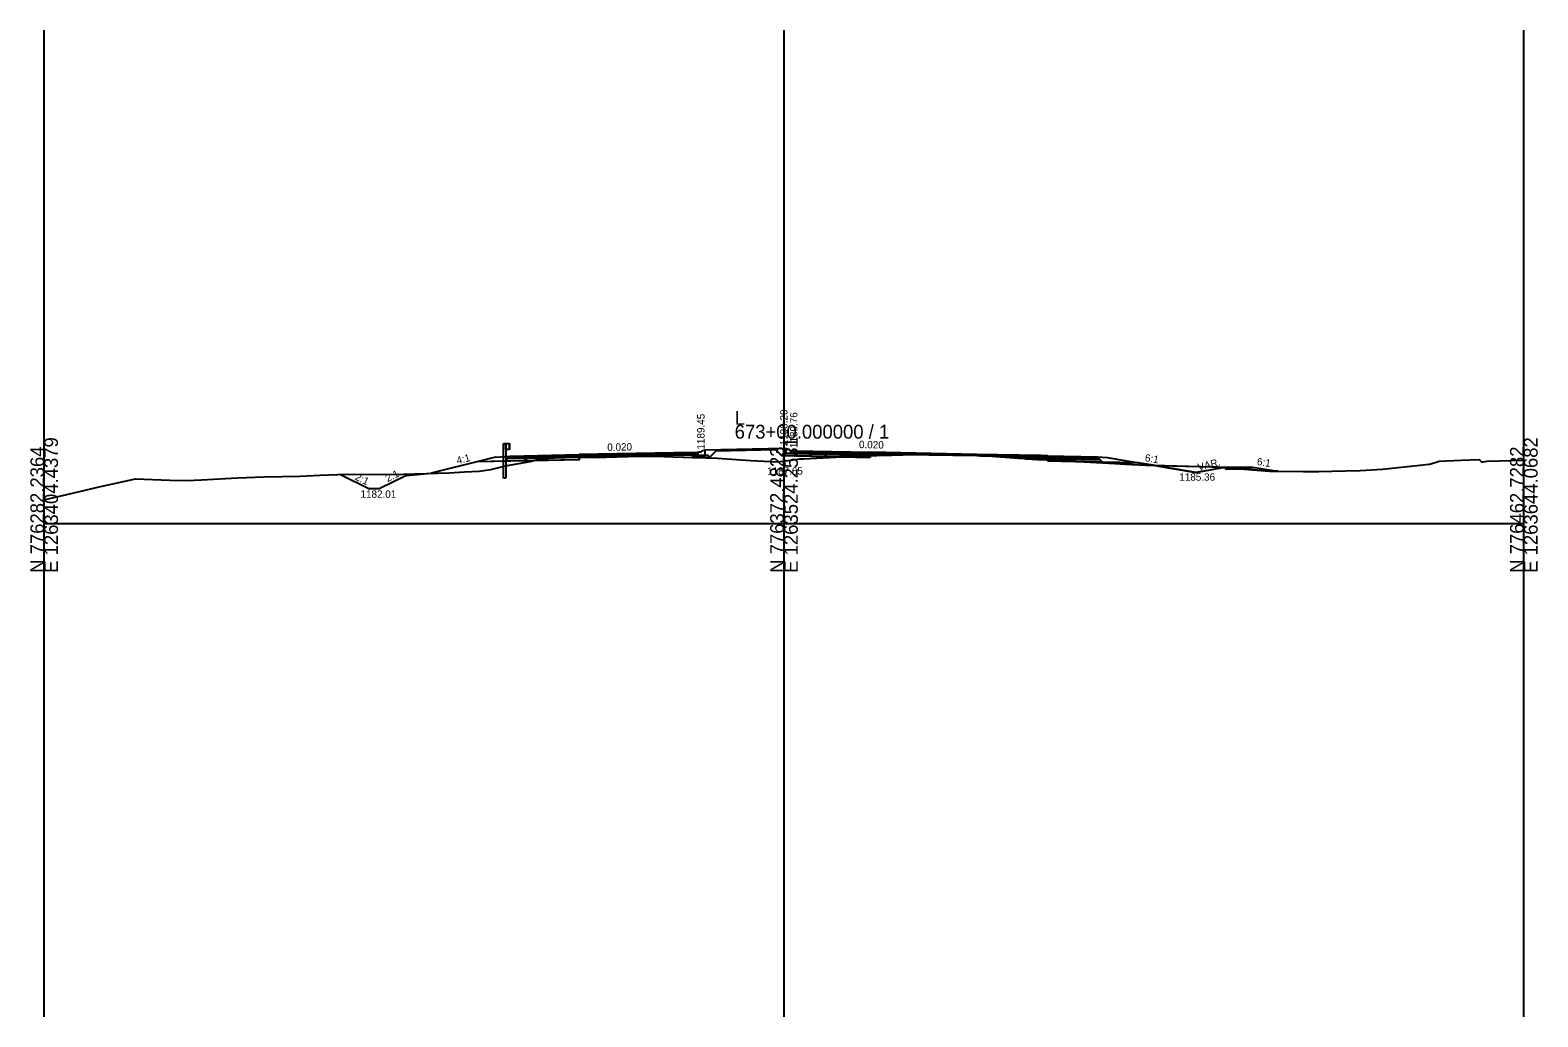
# Model space of a CAD drawing. Extents: x -41 to 1262860, y -100 to 777489.
# Drawn here: x 497.2 to 802.8, y 115 to 315 of the extents above; entities that cross this region are included whole.
import ezdxf

# ---------------------------------------------------------------- set-up
doc = ezdxf.new("R2010")
doc.units = 0
for name, color, linetype in [('Exist Cross Section Cell', 7, 'Continuous'), ('Exist XS Center Line Elevation Label', 7, 'Continuous'), ('Exist XS Ground Line', 7, 'Continuous'), ('Prop CMT Guardrail Graphics', 7, 'Continuous'), ('Prop CMT Pvmt Concrete', 7, 'Continuous'), ('Prop CMT Pvmt Course 1', 7, 'Continuous'), ('Prop CMT Pvmt Course 4', 7, 'Continuous'), ('Prop CMT Pvmt Surface', 7, 'Continuous'), ('Prop CMT Shld Paved Course 1', 7, 'Continuous'), ('Prop CMT Shld Paved Course 2', 7, 'Continuous'), ('Prop CMT Shld Paved Course 4', 7, 'Continuous'), ('Prop CMT Subgrade Earthwork', 7, 'Continuous'), ('Prop Conc Curb and Gutter', 7, 'Continuous'), ('Prop Conc Island Cover', 7, 'Continuous'), ('Prop XS Ditch Standard Text', 7, 'Continuous'), ('Prop XS Earthwork Shape', 7, 'Continuous'), ('Prop XS Elevation Labels', 7, 'Continuous'), ('Prop XS Exc Vertical Line 1', 7, 'Continuous'), ('Prop XS Exc Vertical Line 2', 7, 'Continuous'), ('Prop XS Exc Vertical Line 3', 7, 'Continuous'), ('Prop XS Finish Grade', 7, 'Continuous'), ('Prop XS Hydro Elevations', 7, 'Continuous'), ('Prop XS SE Text', 7, 'Continuous'), ('Prop XS Side Slope Text', 7, 'Continuous'), ('Scratch_Level_1', 7, 'Continuous'), ('Scratch_Level_4', 7, 'Continuous'), ('Scratch_Level_6', 7, 'Continuous')]:
    doc.layers.add(name, color=color, linetype=linetype)

msp = doc.modelspace()

# ---------------------------------------------------------------- linework, layer by layer
at = {"layer": 'Exist Cross Section Cell'}
for p, q in [((650, 215), (650, 235)), ((500, 215), (650, 215)), ((650, 215), (800, 215))]:
    msp.add_line(p, q, dxfattribs=at)
at = {"layer": 'Exist XS Ground Line'}
msp.add_lwpolyline([(500, 219.77), (500.55, 219.9), (506.89, 221.42), (511.4, 222.5), (513.89, 223.03), (518.54, 224.04), (525.5, 223.81), (528.95, 223.71), (531.89, 223.88), (539.2, 224.25), (544.63, 224.43), (551.91, 224.62), (555.97, 224.83), (561.37, 224.97), (569.37, 224.96), (572.82, 225.02), (582.14, 225.28), (585.2, 225.48), (588.22, 225.61), (590.59, 225.97), (593.51, 226.7), (598.55, 227.59), (599.77, 227.93), (601.37, 228.12), (602.72, 228.29), (603.5, 228.3), (607.89, 228.45), (609.08, 228.47), (611.68, 228.37), (620.56, 228.62), (624.04, 228.65), (627.52, 228.54), (636.51, 228.21), (637.48, 228.16), (639.45, 228.06), (643.3, 227.78), (648.7, 227.47), (651.31, 227.83), (653.19, 228.08), (653.8, 228.12), (653.99, 228.13), (662.73, 228.56), (665.83, 228.72), (671.78, 228.88), (677.74, 229.03), (679.36, 229), (689.76, 228.82), (692.13, 228.67), (698.7, 228.16), (699.03, 228.13), (699.07, 228.13), (701.34, 227.96), (703.63, 227.92), (704.66, 227.9), (717.07, 227.15), (719.26, 227), (723.37, 226.84), (736.84, 226.5), (737.79, 226.48), (737.89, 226.48), (738.17, 226.45), (748.46, 225.62), (755.35, 225.55), (758.45, 225.57), (763.86, 225.69), (766.8, 225.72), (771.35, 226.03), (778.98, 226.8), (780.75, 227.01), (780.95, 227.06), (782.86, 227.61), (787.3, 227.84), (790.97, 227.95), (791.05, 227.87), (791.47, 227.45), (791.75, 227.49), (792.54, 227.64), (800, 227.84)], dxfattribs=at)
at = {"layer": 'Prop CMT Guardrail Graphics'}
for p, q in [((593.11, 231.19), (593.59, 231.19)), ((593.11, 228.69), (593.11, 231.19)), ((593.59, 230.01), (593.59, 231.19)), ((593.59, 231.19), (594.26, 231.19)), ((593.59, 231.19), (593.59, 228.68)), ((594.26, 230.01), (593.59, 230.01)), ((594.26, 231.19), (594.26, 230.01)), ((594.26, 231.11), (594.26, 230.09)), ((594.36, 231.09), (594.26, 231.11)), ((594.26, 230.09), (594.36, 230.11)), ((594.27, 230.64), (594.5, 230.84)), ((594.27, 230.55), (594.27, 230.64)), ((594.5, 230.35), (594.27, 230.55)), ((594.5, 230.99), (594.36, 231.09)), ((594.36, 230.11), (594.5, 230.21)), ((594.5, 230.84), (594.5, 230.99)), ((594.5, 230.21), (594.5, 230.35)), ((593.11, 224.18), (593.11, 228.69)), ((593.59, 228.68), (593.59, 224.18)), ((593.59, 224.18), (593.11, 224.18))]:
    msp.add_line(p, q, dxfattribs=at)
at = {"layer": 'Prop CMT Pvmt Concrete'}
for p, q in [((739.5, 226.34), (744.5, 226.44)), ((739.5, 226.34), (739.5, 226.01)), ((744.5, 226.44), (744.5, 226.11)), ((739.5, 226.01), (744.5, 226.11))]:
    msp.add_line(p, q, dxfattribs=at)
at = {"layer": 'Prop CMT Pvmt Course 1'}
for p, q in [((632.5, 229.19), (632.5, 229.44)), ((651.96, 229.75), (651.96, 229.5)), ((651.96, 229.5), (667.5, 229.19)), ((631.5, 229.17), (632.5, 229.19))]:
    msp.add_line(p, q, dxfattribs=at)
for points in [[(608.5, 228.96), (608.5, 228.71), (608.5, 228.71), (631.5, 229.17), (631.5, 229.17), (631.5, 229.42), (631.5, 229.42), (631.5, 229.42), (608.5, 228.96), (608.5, 228.96), (608.5, 228.96)], [(703.5, 228.72), (703.5, 228.72), (702.06, 228.75), (702.06, 228.75), (701.97, 228.75), (701.97, 228.75), (701.97, 228.75), (689.08, 229.01), (689.08, 229.01), (670.64, 229.37), (670.57, 229.38), (670.57, 229.38), (670.45, 229.38), (670.45, 229.38), (670.32, 229.38), (670.32, 229.38), (670.17, 229.38), (670.17, 229.38), (670.04, 229.39), (670.04, 229.39), (669.93, 229.39), (669.93, 229.39), (669.87, 229.39), (669.87, 229.39), (667.5, 229.44), (667.5, 229.44), (667.5, 229.44), (667.5, 229.19), (667.5, 229.19), (669.87, 229.14), (669.87, 229.14), (669.93, 229.14), (669.93, 229.14), (670.04, 229.14), (670.04, 229.14), (670.17, 229.13), (670.17, 229.13), (670.32, 229.13), (670.32, 229.13), (670.45, 229.13), (670.45, 229.13), (670.57, 229.13), (670.57, 229.13), (670.64, 229.12), (689.08, 228.76), (689.08, 228.76), (701.97, 228.5), (701.97, 228.5), (701.97, 228.5), (702.06, 228.5), (702.06, 228.5), (703.5, 228.47), (703.5, 228.72)]]:
    msp.add_lwpolyline(points, dxfattribs=at)
at = {"layer": 'Prop CMT Pvmt Course 4'}
for p in [(593.9, 228.08), (608.5, 227.92)]:
    msp.add_line(p, (593.44, 227.61), dxfattribs=at)
at = {"layer": 'Prop CMT Pvmt Surface'}
for p, q in [((608.5, 228.96), (631.5, 229.42)), ((631.5, 229.42), (632.5, 229.44)), ((651.96, 229.75), (667.5, 229.44)), ((667.5, 229.44), (703.5, 228.72)), ((594.5, 228.68), (608.5, 228.96)), ((703.5, 228.72), (713.5, 228.52))]:
    msp.add_line(p, q, dxfattribs=at)
at = {"layer": 'Prop CMT Shld Paved Course 1'}
for p, q in [((608.5, 228.71), (594.24, 228.42)), ((594.5, 228.68), (594.24, 228.42)), ((604.5, 228.88), (604.5, 228.88)), ((608.5, 228.96), (608.5, 228.71)), ((608.5, 228.71), (608.5, 228.71)), ((703.5, 228.72), (703.5, 228.47)), ((703.5, 228.47), (703.5, 228.47)), ((703.5, 228.47), (713.76, 228.26)), ((707.5, 228.64), (707.5, 228.64)), ((713.76, 228.26), (713.5, 228.52))]:
    msp.add_line(p, q, dxfattribs=at)
at = {"layer": 'Prop CMT Shld Paved Course 2'}
for p, q in [((651.96, 229.16), (651.96, 229.5)), ((593.9, 228.08), (594.24, 228.42)), ((608.5, 228.37), (593.9, 228.08)), ((603.9, 228.28), (603.9, 228.28)), ((603.9, 228.28), (603.9, 228.28)), ((608.5, 228.71), (609.08, 228.72)), ((608.5, 228.71), (608.5, 228.37)), ((608.5, 228.46), (608.5, 228.71)), ((608.5, 228.71), (608.5, 228.71)), ((609.08, 228.47), (608.5, 228.46)), ((608.5, 228.37), (608.5, 228.37)), ((609.08, 228.72), (611.68, 228.77)), ((609.08, 228.72), (609.08, 228.72)), ((610.49, 228.41), (609.08, 228.47)), ((609.08, 228.47), (609.08, 228.47)), ((611.68, 228.44), (610.49, 228.41)), ((610.49, 228.41), (610.49, 228.41)), ((611.68, 228.77), (620.56, 228.95)), ((611.68, 228.77), (611.68, 228.77)), ((611.68, 228.77), (611.68, 228.77)), ((619.49, 228.59), (611.68, 228.44)), ((611.68, 228.44), (611.68, 228.44)), ((620.56, 228.62), (619.49, 228.59)), ((619.49, 228.59), (619.49, 228.59)), ((620.56, 228.95), (624.04, 229.02)), ((620.56, 228.95), (620.56, 228.95)), ((621.34, 228.63), (620.56, 228.62)), ((624.04, 228.68), (621.34, 228.63)), ((624.04, 229.02), (627.52, 229.09)), ((627.52, 228.75), (624.04, 228.68)), ((624.04, 228.68), (624.04, 228.68)), ((627.52, 229.09), (631.5, 229.17)), ((627.52, 229.09), (627.52, 229.09)), ((627.52, 229.09), (627.52, 229.09)), ((627.52, 229.09), (627.52, 229.09)), ((631.5, 228.83), (627.52, 228.75)), ((627.52, 228.75), (627.52, 228.75)), ((627.52, 228.75), (627.52, 228.75)), ((627.52, 228.75), (627.52, 228.75)), ((631.5, 229.17), (631.5, 229.17)), ((631.5, 229.17), (631.5, 229.17)), ((631.5, 229.17), (631.5, 228.83)), ((631.5, 228.83), (632.5, 228.85)), ((631.5, 228.83), (631.5, 228.83)), ((632.5, 229.19), (632.5, 228.85)), ((651.96, 229.16), (667.5, 228.85)), ((669.87, 229.14), (667.5, 229.19)), ((667.5, 229.19), (667.5, 229.19)), ((667.5, 229.19), (667.5, 229.19)), ((667.5, 229.19), (667.5, 229.19)), ((667.5, 229.19), (667.5, 228.85)), ((667.5, 228.85), (667.5, 228.85)), ((667.5, 228.85), (669.45, 228.81)), ((669.45, 228.81), (669.87, 228.83)), ((669.45, 228.81), (669.45, 228.81)), ((669.45, 228.81), (669.45, 228.81)), ((669.93, 229.14), (669.87, 229.14)), ((669.87, 229.14), (669.87, 229.14)), ((669.87, 228.83), (669.87, 228.83)), ((669.87, 228.83), (669.93, 228.83)), ((670.04, 229.14), (669.93, 229.14)), ((669.93, 229.14), (669.93, 229.14)), ((669.93, 228.83), (669.93, 228.83)), ((669.93, 228.83), (670.04, 228.83)), ((670.17, 229.13), (670.04, 229.14)), ((670.04, 229.14), (670.04, 229.14)), ((670.04, 228.83), (670.04, 228.83)), ((670.04, 228.83), (670.17, 228.83)), ((670.32, 229.13), (670.17, 229.13)), ((670.17, 229.13), (670.17, 229.13)), ((670.17, 228.83), (670.32, 228.84)), ((670.17, 228.83), (670.17, 228.83)), ((670.45, 229.13), (670.32, 229.13)), ((670.32, 229.13), (670.32, 229.13)), ((670.32, 228.84), (670.32, 228.84)), ((670.32, 228.84), (670.45, 228.84)), ((670.57, 229.13), (670.45, 229.13)), ((670.45, 229.13), (670.45, 229.13)), ((670.45, 228.84), (670.57, 228.85)), ((670.45, 228.84), (670.45, 228.84)), ((670.64, 229.12), (670.57, 229.13)), ((670.57, 229.13), (670.57, 229.13)), ((670.57, 228.85), (670.57, 228.85)), ((670.57, 228.85), (670.64, 228.85)), ((671.78, 229.1), (670.64, 229.12)), ((670.64, 228.85), (671.78, 228.88)), ((677.74, 228.98), (671.78, 229.1)), ((671.78, 229.1), (671.78, 229.1)), ((671.78, 228.88), (676.62, 229)), ((671.78, 228.88), (671.78, 228.88)), ((676.62, 229), (676.62, 229)), ((676.62, 229), (677.74, 228.98)), ((679.36, 228.95), (677.74, 228.98)), ((677.74, 228.98), (679.36, 228.95)), ((689.08, 228.76), (679.36, 228.95)), ((679.36, 228.95), (679.36, 228.95)), ((679.36, 228.95), (679.36, 228.95)), ((679.36, 228.95), (689.08, 228.76)), ((689.76, 228.74), (689.08, 228.76)), ((689.08, 228.76), (689.08, 228.76)), ((689.08, 228.76), (689.08, 228.76)), ((689.08, 228.76), (689.76, 228.74)), ((692.13, 228.69), (689.76, 228.74)), ((689.76, 228.74), (689.76, 228.74)), ((689.76, 228.74), (689.76, 228.74)), ((689.76, 228.74), (691.5, 228.71)), ((691.5, 228.71), (691.5, 228.71)), ((691.5, 228.71), (691.5, 228.71)), ((691.5, 228.71), (692.13, 228.67)), ((698.7, 228.56), (692.13, 228.69)), ((692.13, 228.69), (692.13, 228.69)), ((692.13, 228.69), (692.13, 228.69)), ((692.13, 228.67), (692.13, 228.67)), ((692.13, 228.67), (692.13, 228.67)), ((692.13, 228.67), (697.45, 228.25)), ((697.45, 228.25), (697.45, 228.25)), ((697.45, 228.25), (698.7, 228.23)), ((699.03, 228.56), (698.7, 228.56)), ((698.7, 228.56), (698.7, 228.56)), ((698.7, 228.23), (699.03, 228.22)), ((699.07, 228.56), (699.03, 228.56)), ((699.03, 228.22), (699.07, 228.22)), ((701.34, 228.51), (699.07, 228.56)), ((699.07, 228.56), (699.07, 228.56)), ((699.07, 228.56), (699.07, 228.56)), ((699.07, 228.22), (699.07, 228.22)), ((699.07, 228.22), (699.07, 228.22)), ((699.07, 228.22), (699.07, 228.22)), ((699.07, 228.22), (701.34, 228.18)), ((701.97, 228.5), (701.34, 228.51)), ((701.34, 228.51), (701.34, 228.51)), ((701.34, 228.18), (701.34, 228.18)), ((701.34, 228.18), (701.97, 228.16)), ((702.06, 228.5), (701.97, 228.5)), ((701.97, 228.16), (702.06, 228.16)), ((703.5, 228.47), (702.06, 228.5)), ((702.06, 228.5), (702.06, 228.5)), ((702.06, 228.16), (702.06, 228.16)), ((702.06, 228.16), (703.5, 228.13)), ((703.5, 228.47), (703.5, 228.13)), ((703.5, 228.47), (703.5, 228.47)), ((703.5, 228.13), (703.5, 228.47)), ((703.5, 228.47), (703.5, 228.47)), ((703.5, 228.47), (703.5, 228.47)), ((703.5, 228.47), (703.5, 228.47)), ((703.5, 228.13), (703.5, 228.13)), ((703.5, 228.13), (714.1, 227.92)), ((703.5, 228.13), (703.5, 228.13)), ((703.5, 228.13), (703.5, 228.13)), ((703.5, 228.13), (703.5, 228.13)), ((714.1, 227.92), (713.76, 228.26))]:
    msp.add_line(p, q, dxfattribs=at)
at = {"layer": 'Prop CMT Shld Paved Course 4'}
for p, q in [((597.4, 228.15), (597.9, 228.16)), ((603.9, 228.28), (603.9, 228.28)), ((608.5, 228.37), (608.5, 227.92)), ((611.68, 228.37), (610.49, 228.41)), ((619.49, 228.59), (611.68, 228.37)), ((621.34, 228.63), (624.04, 228.65)), ((627.52, 228.54), (624.04, 228.65)), ((627.52, 228.54), (631.5, 228.39)), ((631.5, 228.38), (631.5, 228.83)), ((631.5, 228.38), (634.95, 228.44)), ((632.5, 228.85), (634.5, 228.89)), ((634.5, 228.89), (634.95, 228.44)), ((649.96, 229.2), (649.51, 228.76)), ((649.51, 228.76), (667.5, 228.4)), ((651.96, 229.16), (649.96, 229.2)), ((667.5, 228.85), (667.5, 228.4)), ((669.45, 228.81), (667.5, 228.76)), ((697.45, 228.25), (698.7, 228.16)), ((699.03, 228.13), (698.7, 228.16)), ((699.07, 228.13), (699.03, 228.13)), ((701.34, 227.96), (699.07, 228.13)), ((703.5, 227.92), (701.34, 227.96)), ((703.5, 228.13), (703.5, 227.68)), ((703.5, 227.68), (714.56, 227.45)), ((714.56, 227.45), (714.1, 227.92))]:
    msp.add_line(p, q, dxfattribs=at)
at = {"layer": 'Prop CMT Subgrade Earthwork'}
for p, q in [((634.95, 228.44), (636.44, 229.93)), ((649.51, 228.76), (648.1, 230.17)), ((608.5, 227.92), (587.75, 227.5)), ((608.5, 227.92), (608.5, 228.46)), ((634.95, 228.44), (631.5, 228.38)), ((631.5, 228.38), (631.5, 228.39)), ((649.51, 228.76), (667.5, 228.4)), ((667.5, 228.4), (667.5, 228.76)), ((703.5, 227.92), (703.5, 227.68)), ((703.5, 227.68), (721.78, 227.31))]:
    msp.add_line(p, q, dxfattribs=at)
at = {"layer": 'Prop Conc Curb and Gutter'}
for p, q in [((633.19, 229.45), (632.5, 229.44)), ((632.5, 229.44), (632.5, 228.85)), ((633.25, 229.53), (633.25, 229.51)), ((634, 229.88), (633.35, 229.67)), ((634, 228.88), (634, 229.88)), ((650.46, 230.19), (651.11, 229.98)), ((650.46, 229.19), (650.46, 230.19)), ((651.21, 229.84), (651.21, 229.82)), ((651.27, 229.76), (651.96, 229.75)), ((651.96, 229.16), (651.96, 229.75)), ((632.5, 228.85), (634, 228.88)), ((634, 228.88), (634, 228.88)), ((651.96, 229.16), (650.46, 229.19))]:
    msp.add_line(p, q, dxfattribs=at)
for centre, radius, start, end in [((633.19, 229.51), 0.0625, 271.1458, 360), ((633.4, 229.53), 0.146, 108.435, 180), ((651.07, 229.84), 0.146, 0, 71.565), ((651.27, 229.82), 0.0625, 180, 268.8542)]:
    msp.add_arc(centre, radius, start, end, dxfattribs=at)
at = {"layer": 'Prop Conc Island Cover'}
for p, q in [((650, 230.2), (634, 229.88)), ((634, 229.62), (634, 229.62)), ((650, 230.2), (650.46, 230.19)), ((650, 229.95), (650.46, 229.94))]:
    msp.add_line(p, q, dxfattribs=at)
at = {"layer": 'Prop XS Earthwork Shape'}
for points in [[(653.19, 228.08), (653.8, 228.12), (653.99, 228.13), (661.77, 228.51), (649.51, 228.76), (648.35, 229.92), (636.18, 229.68), (634.95, 228.44), (631.84, 228.38), (636.51, 228.21), (637.48, 228.16), (639.45, 228.06), (643.3, 227.78), (648.7, 227.47), (651.31, 227.83)], [(593.44, 227.61), (587.75, 227.5), (578.45, 225.18), (582.14, 225.28), (585.2, 225.48), (588.22, 225.61), (590.59, 225.97), (593.51, 226.7), (598.55, 227.59), (599.04, 227.73)], [(599.04, 227.73), (599.77, 227.93), (601.37, 228.12), (602.72, 228.29), (603.5, 228.3), (607.89, 228.45), (608.5, 228.46), (608.5, 227.92)], [(631.5, 228.38), (631.5, 228.39), (631.84, 228.38)], [(667.5, 228.4), (667.5, 228.76), (665.83, 228.72), (662.73, 228.56), (661.77, 228.51)], [(703.5, 227.92), (703.63, 227.92), (704.66, 227.9), (710.86, 227.53), (703.5, 227.68)], [(710.86, 227.53), (717.07, 227.15), (719.26, 227), (723.37, 226.84), (724.85, 226.8), (721.78, 227.31), (714.56, 227.45)], [(737.79, 226.48), (737.89, 226.48), (738.17, 226.45), (739.5, 226.34), (733.5, 225.36), (724.85, 226.8), (736.84, 226.5)], [(744.5, 226.44), (745, 226.45), (750.1, 225.6), (748.46, 225.62), (739.5, 226.34)]]:
    msp.add_lwpolyline(points, close=True, dxfattribs=at)
at = {"layer": 'Prop XS Exc Vertical Line 1'}
msp.add_line((500, 115), (500, 315), dxfattribs=at)
at = {"layer": 'Prop XS Exc Vertical Line 2'}
msp.add_line((650, 115), (650, 315), dxfattribs=at)
at = {"layer": 'Prop XS Exc Vertical Line 3'}
msp.add_line((800, 115), (800, 315), dxfattribs=at)
at = {"layer": 'Prop XS Finish Grade'}
for p, q in [((591.5, 228.44), (578.45, 225.18)), ((591.5, 228.44), (594.5, 228.68)), ((594.5, 228.68), (593.44, 227.61)), ((713.5, 228.52), (715.5, 228.36)), ((713.5, 228.52), (714.56, 227.45)), ((715.5, 228.36), (733.5, 225.36)), ((733.5, 225.36), (739, 226.33)), ((744.5, 226.44), (739, 226.33)), ((744.5, 226.44), (745, 226.45)), ((745, 226.45), (750.1, 225.6)), ((560.11, 224.93), (565.95, 222.01)), ((573.45, 224.76), (567.95, 222.01)), ((573.45, 224.76), (578.45, 225.18)), ((567.95, 222.01), (565.95, 222.01))]:
    msp.add_line(p, q, dxfattribs=at)
at = {"layer": 'Scratch_Level_1'}
msp.add_lwpolyline([(744.5, 226.44), (739.5, 226.34), (736.73, 226.51)], dxfattribs=at)
at = {"layer": 'Scratch_Level_4'}
msp.add_line((800, 115), (800, 315), dxfattribs=at)
at = {"layer": 'Scratch_Level_6'}
msp.add_line((500, 115), (500, 315), dxfattribs=at)

# ---------------------------------------------------------------- texts
at = {"layer": 'Exist Cross Section Cell'}
for s, p in [('L', (640, 235)), ('673+00.000000 / 1', (640, 232.2))]:
    msp.add_text(s, height=2.8, dxfattribs=at).set_placement(p)
for s, p in [('N 776282.2364', (500, 205)), ('E 1263404.4379', (502.8, 205)), ('N 776372.4823', (650, 205)), ('E 1263524.2531', (652.8, 205)), ('N 776462.7282', (800, 205)), ('E 1263644.0682', (802.8, 205))]:
    msp.add_text(s, height=2.8, rotation=90, dxfattribs=at).set_placement(p)
at = {"layer": 'Exist XS Center Line Elevation Label'}
msp.add_text('1187.65', height=1.5, dxfattribs=at).set_placement((646.57, 224.9))
at = {"layer": 'Prop XS Ditch Standard Text'}
for s, p in [('1185.36', (730.15, 223.67)), ('1182.01', (564.14, 220.21))]:
    msp.add_text(s, height=1.5, dxfattribs=at).set_placement(p)
at = {"layer": 'Prop XS Elevation Labels'}
for s, p in [('1189.45', (633.89, 229.99)), ('1189.76', (652.72, 230.3))]:
    msp.add_text(s, height=1.5, rotation=90, dxfattribs=at).set_placement(p)
at = {"layer": 'Prop XS Hydro Elevations'}
msp.add_text('1190.20', height=1.5, rotation=90, dxfattribs=at).set_placement((650.71, 230.85))
at = {"layer": 'Prop XS SE Text'}
for rotation, p in [(1.1458, (614.18, 229.71)), (358.8542, (665.19, 230.28))]:
    msp.add_text('0.020', height=1.5, rotation=rotation, dxfattribs=at).set_placement(p)
at = {"layer": 'Prop XS Side Slope Text'}
for s, rotation, p in [('4:1', 14.0362, (583.79, 227)), ('6:1', 350.5377, (723.09, 227.63)), ('VAR.', 14.2871, (734.08, 225.65)), ('6:1', 350.5377, (745.8, 226.89)), ('2:1', 333.6935, (562.89, 223.96)), ('2:1', 26.5651, (569.64, 223.36))]:
    msp.add_text(s, height=1.5, rotation=rotation, dxfattribs=at).set_placement(p)

doc.saveas('drawing.dxf')
